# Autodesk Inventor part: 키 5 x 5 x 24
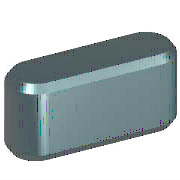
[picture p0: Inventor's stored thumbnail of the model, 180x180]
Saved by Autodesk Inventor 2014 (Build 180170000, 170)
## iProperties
IsCustomPart: 1
Created: 2012-02
Part Number: 키 5 x 5 x 24
Material: 강철, 연강
Description: 키 및 해당 키홈
Document SubType Name: Modeling
Standard: KS B 1311
Designer: mduedu
Standards Organization: KS
Language: ko-KR
Size Designation: 5 x 5 x 18
Categories: <MemberInstance><Categories><Category DisplayName="샤프트 부품" InternalName="7f7aeb1f-a693-4053-b835-cee3144e0d98" Mnemonic="SHFT"><Category DisplayName="키" Interna
Density: 7.86 g/cm^3
Mass: 4.43866 g
Surface Area: 4.72224 cm^2
Volume: 0.564716 cm^3
Appearance: 금색
Author: mduedu
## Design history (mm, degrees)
workplane "Work Plane1"
workplane "Work Plane2"
sketch "스케치1"
  geometry: L1 (2.5, 2.5)-(21.5, 2.5); L2 (21.5, -2.5)-(2.5, -2.5); L3 (0, 8.9)-(0, -4.4) reference; L4 (-3.6, 0)-(21.6, 0) reference; L5 (24, 0)-(24, 7); A1 r 2.5 centre (2.5, 0) between (2.5, 2.5) and (2.5, -2.5); A2 r 2.5 centre (21.5, 0) between (21.5, -2.5) and (21.5, 2.5)
  constraints: 6 end point, 5 point on circle, 4 tangent, 3 point on line, 2 centre point, 1 horizontal, 1 parallel, 1 perpendicular
  dimensions: "d0" = 2.5 radius of A1 (= 0.5 x PB); "d13" = 2.5 radius of A2 (= 0.5 x PB); "d14" = 24 distance between parallel lines of L5 L3 (= NLG)
extrude "본체1" new body sketch "스케치1" taper "d3" = 0 deg; stored distance "d4" = 10
workplane "Work Plane3"
body "Solid1"
chamfer "모따기1" distance "d8" = 0.4 (= PHH); stored, may be unused: second distance "d9" = 0.4 (= PHH), angle "d15" = 45 deg
other parameters: "d1" = -3 (= -PNT), "d2" = 2 (= PH - PNT), "NLG" = 24 [user parameter; used in 3 equation terms], "PB" = 5 [user parameter; used in 2 equation terms], "PNT" = 3 [user parameter; used in 2 equation terms], "PH" = 5 [user parameter; used in 1 equation term], "PHH" = 0.4 [user parameter; used in 2 equation terms], "d10" = 0, "d16" = 0, "d17" = 0, "d18" = 0, "WDMIN" = 12 [user parameter], "PLB2" = 24 (= NLG) [user parameter], "WDMAX" = 17 [user parameter], "PLB1" = 24 (= NLG) [user parameter], "RR" = 0.16 [user parameter], "PUEB" = 2.3 [user parameter]
